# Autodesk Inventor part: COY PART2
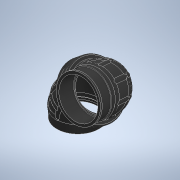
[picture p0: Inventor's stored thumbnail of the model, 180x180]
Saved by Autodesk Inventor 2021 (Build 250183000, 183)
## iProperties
Created: 2024-06
Part Number: COY PART2
Material: Generic
Document SubType Name: Modeling
Designer: nick9
Density: 1 g/cm^3
Appearance: Default
Author: nick9
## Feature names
1. Extrusion1
2. Extrusion2
3. Revolution1
4. Sweep1
5. Revolution2
6. Fillet1
7. Extrusion3
8. Sweep3
9. Extrusion4
10. Extrusion5
11. Fillet2
12. Revolution3
13. Extrusion6
14. Fillet3
15. Chamfer1
16. Sweep5
17. Revolution4
18. Circular Pattern1
19. Sweep6
20. Revolution5
21. Circular Pattern2
22. Fillet8
23. Extrusion7
24. Fillet12
25. Fillet13
26. Loft4
27. Fillet14
28. Fillet15
29. Fillet16
30. Loft6
31. Loft8
32. Loft9
33. Chamfer2
34. Chamfer3
35. Chamfer4
36. Chamfer5
37. Chamfer6
38. Chamfer7
39. Chamfer8
40. Chamfer9
41. Chamfer10
42. Chamfer11
43. Chamfer12
44. Chamfer13
## Parameters: d0 = 78.486 mm, d3 = 86.106 mm, d4 = 9.525 mm, d5 = 0, d6 = 75.946 mm, d7 = 86.106 mm, d8 = 7.112 mm, d9 = 0, d11 = 1.651 mm, d12 = 4.318 mm, d13 = 0.381 mm, d14 = 90 deg, d15 = 86.106 mm, d16 = 50.165 mm, d17 = 0, d18 = 0, d19 = 35.56 mm, d20 = 7.3025 mm, d21 = 43.053 mm, d22 = 37.973 mm, d23 = 9.41917 mm, d24 = 9.41917 mm, d25 = 9.41917 mm, d26 = 9.41917 mm, d27 = 53.975 mm, d28 = 42.58945 mm, d32 = 5.588 mm, d33 = 5.588 mm, d34 = 5.588 mm, d36 = 1.524 mm, d37 = 1.524 mm, d39 = 2.032 mm, d40 = 5.08 mm, d41 = 90 deg, d42 = 3.175 mm, d54 = 0.254 mm, d55 = 0, d56 = 6.35 mm, d57 = 0, d59 = 97 deg, d60 = 7.62 mm, d62 = 0, d63 = 0, d64 = 45.466 mm, d65 = 25.4 mm, d66 = 0, d68 = 1.0795 mm, d70 = 1.10009 mm, d71 = -25.4 mm, d72 = 75.946 mm, d73 = 69.596 mm, d74 = 3.175 mm, d75 = 0, d76 = 35.56 mm, d77 = 3.96875 mm, d78 = 20.6375 mm, d79 = 1.5875 mm, d83 = 90 deg, d84 = 2.794 mm, d85 = 5 deg, d87 = 4.191 mm, d88 = 0, d89 = 0.762 mm, d90 = 1.5875 mm, d91 = 3.175 mm, d92 = 45 deg, d93 = -19.812 mm, d94 = 1.397 mm, d95 = 8.636 mm, d100 = 360 deg, d103 = 5 deg, d104 = 3.175 mm, d105 = 0, d106 = 0, d107 = 19.812 mm, d108 = 1.397 mm, d109 = 8.636 mm, d110 = 180 deg, d112 = 41 deg, d122 = 8.8392 mm, d123 = 1.397 mm, d124 = 8.636 mm, d127 = 360 deg, d129 = 0, d130 = 5 deg, d131 = 0, d132 = 0, d134 = 1.397 mm, d135 = 8.636 mm, d136 = 86 deg, d137 = 95 deg, d139 = 78 deg, d145 = 3.175 mm, d148 = 3.175 mm, d150 = 92.68251 mm, d151 = 13.97 mm, d153 = 0.127 mm, d154 = 0.127 mm, d156 = 6.35 mm, d157 = 0, d158 = 0.254 mm, d163 = 0.254 mm, d164 = 0, d165 = 90 deg, d166 = 0, d167 = 90 deg, d168 = 0.254 mm, d173 = 0.254 mm, d174 = 0.254 mm, d179 = 0, d180 = 90 deg, d181 = 0, d182 = 90 deg, d183 = 0.0254 mm, d184 = 0.0254 mm, d189 = 0.0254 mm, d190 = 0.0254 mm, d191 = 0, d192 = 90 deg, d193 = 0, d194 = 90 deg, d195 = 0, d196 = 90 deg, d197 = 0, d198 = 90 deg, d208 = 4.2672 mm, d209 = 3.175 mm, d210 = 45 deg, d211 = 4.191 mm, d212 = 3.7211 mm, d213 = 45 deg, d214 = 0.9906 mm, d215 = 3.7211 mm, d216 = 45 deg, d217 = 0.9906 mm, d218 = 3.7211 mm, d219 = 45 deg, d220 = 3.175 mm, d221 = 3.556 mm, d222 = 45 deg, d225 = 3.048 mm, d226 = 3.556 mm, d227 = 45 deg, d228 = 0.254 mm, d229 = 3.556 mm, d230 = 45 deg, d231 = 0.508 mm, d232 = 3.556 mm, d233 = 45 deg, d234 = 0.508 mm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
